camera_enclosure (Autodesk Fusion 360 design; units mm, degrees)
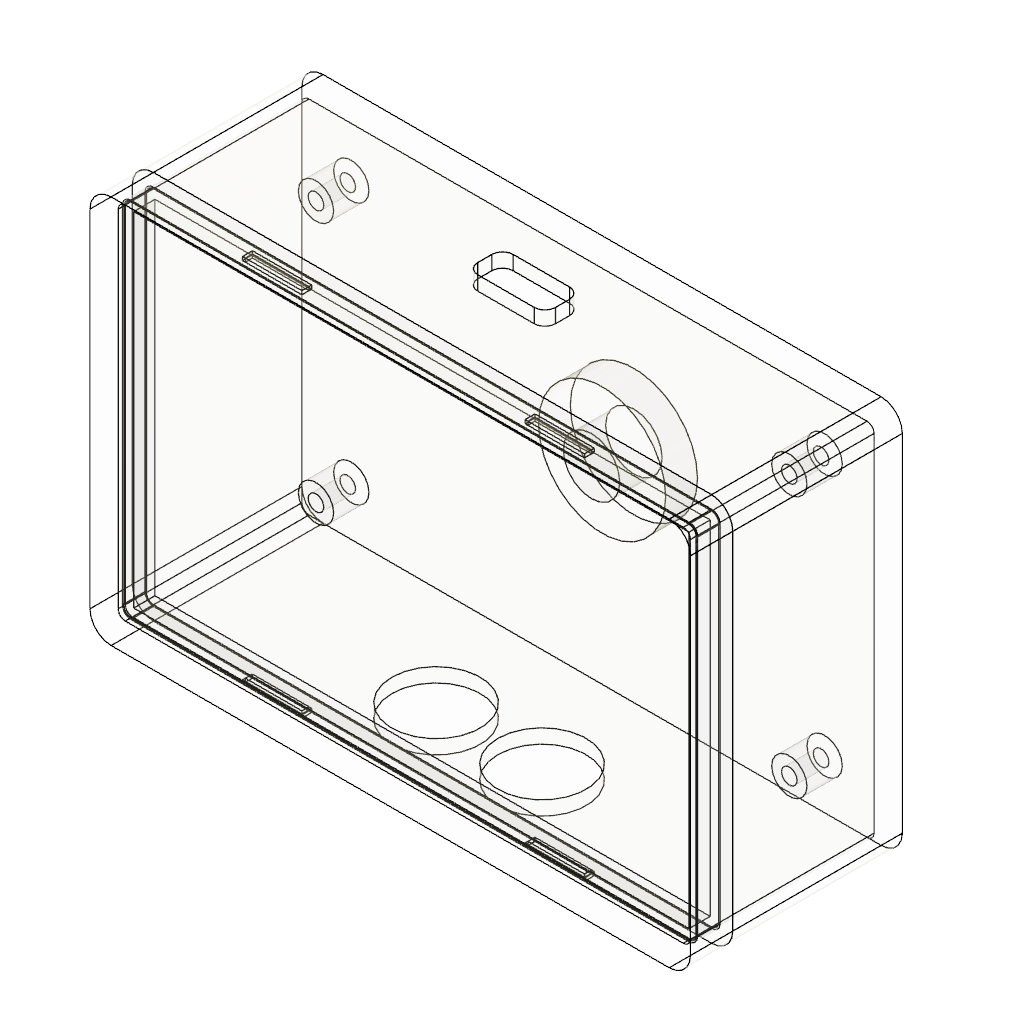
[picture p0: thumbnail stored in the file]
part number: 2026-10-16-16-51-44-539
parameter "User Parameter" = 0 (= "job ae3369b9")
parameter "encL" = 85 comment "job ae3369b9"
parameter "encW" = 55 comment "job ae3369b9"
parameter "encH" = 30 comment "job ae3369b9"
parameter "wall" = 2 comment "job ae3369b9"
parameter "Rv" = 3 comment "job ae3369b9"
parameter "split" = 24 comment "job ae3369b9"
parameter "lipT" = 1.2 comment "job ae3369b9"
parameter "lipH" = 3 comment "job ae3369b9"
parameter "clr" = 0.2 comment "job ae3369b9"
parameter "lensD" = 12.5 comment "job ae3369b9"
parameter "lensPitch" = 15 comment "job ae3369b9"
parameter "lensZ" = 16 comment "job ae3369b9"
parameter "usbW" = 11 comment "job ae3369b9"
parameter "usbH" = 5 comment "job ae3369b9"
parameter "usbR" = 1.5 comment "job ae3369b9"
parameter "usbZ" = 8.6 comment "job ae3369b9"
parameter "soOD" = 5 comment "job ae3369b9"
parameter "soID" = 2.2 comment "job ae3369b9"
parameter "soH" = 5 comment "job ae3369b9"
parameter "soPx" = 67 comment "job ae3369b9"
parameter "soPy" = 37 comment "job ae3369b9"
parameter "bossD" = 18 comment "job ae3369b9"
parameter "bossH" = 4.5 comment "job ae3369b9"
parameter "insD" = 8 comment "job ae3369b9"
parameter "insDepth" = 6 comment "job ae3369b9"
parameter "snapL" = 8 comment "job ae3369b9"
parameter "snapP" = 0.5 comment "job ae3369b9"
parameter "snapX" = 20 comment "job ae3369b9"
sketch "Outline" plane through (0, 0, 0) normal (0, 0, 1) x axis (1, 0, 0)
  line L1 (-42.5, 27.5) -> (42.5, 27.5)
  line L2 (-42.5, -27.5) -> (-42.5, 27.5)
  line L3 (42.5, -27.5) -> (-42.5, -27.5)
  line L4 (42.5, 27.5) -> (42.5, -27.5)
extrude "Extrude1" new body sketch "Outline" along normal blind 30 (= "encH") bodies "Tub"
fillet "Fillet1" radius 3 (= "Rv")
shell "Shell1" innerThickness 2 (= "wall")
work_plane "WorkPlane1" sketch "LidClearance" AlongDistance 2 (= "wall") ExtraOffset 0
sketch "Standoffs" plane through (0, 0, 2) normal (0, 0, 1) x axis (1, 0, 0)
  circle C1 centre (-33.5, -18.5) radius 2.5
  circle C2 centre (-33.5, 18.5) radius 2.5
  circle C3 centre (33.5, -18.5) radius 2.5
  circle C4 centre (33.5, 18.5) radius 2.5
extrude "Extrude2" add sketch "Standoffs" along normal blind 5 (= "soH")
work_plane "WorkPlane2" sketch "LidClearance" AlongDistance 7 (= "wall + soH") ExtraOffset 0
sketch "StandoffHoles" plane through (0, 0, 7) normal (0, 0, 1) x axis (1, 0, 0)
  circle C1 centre (-33.5, -18.5) radius 1.1
  circle C2 centre (-33.5, 18.5) radius 1.1
  circle C3 centre (33.5, -18.5) radius 1.1
  circle C4 centre (33.5, 18.5) radius 1.1
extrude "Extrude3" cut sketch "StandoffHoles" against normal blind 4.5 (magnitude of "-( soH - 0.5 mm )")
sketch "TripodBoss" plane through (0, 0, 0) normal (0, 0, 1) x axis (1, 0, 0)
  circle C1 centre (0, 0) radius 9
extrude "Extrude4" add sketch "TripodBoss" no distance stored
work_plane "WorkPlane3" sketch "LidClearance" ExtraOffset 0
sketch "InsertPocket" plane through (0, 0, -4.5) normal (0, 0, 1) x axis (1, 0, 0)
  circle C1 centre (0, 0) radius 4
extrude "Extrude5" cut sketch "InsertPocket" along normal blind 6 (= "insDepth")
sketch "LensHoles" plane through (0, -27.5, 0) normal (0, -1, 0) x axis (1, 0, 0)
  line L1 (-39.5, 0) -> (-39.5, 30)
  line L2 (39.5, 0) -> (-39.5, 0)
  line L3 (39.5, 30) -> (39.5, 0)
  line L4 (-39.5, 30) -> (39.5, 30)
  circle C1 centre (-7.5, 16) radius 6.25
  circle C2 centre (7.5, 16) radius 6.25
extrude "Extrude6" cut sketch "LensHoles" profile of C1 C2 against normal blind 3 (magnitude of "-( wall + 1 mm )")
sketch "USBC" plane through (0, 27.5, 0) normal (0, 1, 0) x axis (-1, 0, 0)
  line L1 (-39.5, 0) -> (-39.5, 30)
  line L2 (39.5, 0) -> (-39.5, 0)
  line L3 (39.5, 30) -> (39.5, 0)
  line L4 (-39.5, 30) -> (39.5, 30)
  line L5 (4, 13.6) -> (-4, 13.6)
  line L6 (5.5, 10.1) -> (5.5, 12.1)
  line L7 (-4, 8.6) -> (4, 8.6)
  line L8 (-5.5, 12.1) -> (-5.5, 10.1)
  arc A1 centre (4, 12.1) radius 1.5 clockwise from (4, 13.6) to (5.5, 12.1)
  arc A2 centre (4, 10.1) radius 1.5 clockwise from (5.5, 10.1) to (4, 8.6)
  arc A3 centre (-4, 10.1) radius 1.5 clockwise from (-4, 8.6) to (-5.5, 10.1)
  arc A4 centre (-4, 12.1) radius 1.5 clockwise from (-5.5, 12.1) to (-4, 13.6)
  tangent L5 A1
  tangent L6 A1
  tangent L6 A2
  tangent L7 A2
  tangent L7 A3
  tangent L8 A3
  tangent L8 A4
  tangent L5 A4
extrude "Extrude7" cut sketch "USBC" profile of L5 L6 L7 L8 A1 A2 A3 A4 against normal blind 3 (magnitude of "-( wall + 1 mm )")
work_plane "WorkPlane4" AlongDistance 24 (= "split") ExtraOffset 0
split "Split1" bodies "Lid"
sketch "Lip" plane through (0, 0, 24) normal (0, 0, 1) x axis (1, 0, 0)
  line L1 (-39.5, 25.5) -> (39.5, 25.5)
  line L2 (-40.5, -24.5) -> (-40.5, 24.5)
  line L3 (39.5, -25.5) -> (-39.5, -25.5)
  line L4 (40.5, 24.5) -> (40.5, -24.5)
  line L5 (-39.3, 24.3) -> (39.3, 24.3)
  line L6 (-39.3, -24.3) -> (-39.3, 24.3)
  line L7 (39.3, -24.3) -> (-39.3, -24.3)
  line L8 (39.3, 24.3) -> (39.3, -24.3)
  arc A1 centre (-39.5, 24.5) radius 1 clockwise from (-40.5, 24.5) to (-39.5, 25.5)
  arc A2 centre (-39.5, -24.5) radius 1 clockwise from (-39.5, -25.5) to (-40.5, -24.5)
  arc A3 centre (39.5, -24.5) radius 1 clockwise from (40.5, -24.5) to (39.5, -25.5)
  arc A4 centre (39.5, 24.5) radius 1 clockwise from (39.5, 25.5) to (40.5, 24.5)
  tangent L1 A1
  tangent L2 A1
  tangent L2 A2
  tangent L3 A2
  tangent L3 A3
  tangent L4 A3
  tangent L4 A4
  tangent L1 A4
extrude "Extrude8" add sketch "Lip" along normal blind 3 (= "lipH")
sketch "LidClearance" plane through (0, 0, 24) normal (0, 0, 1) x axis (1, 0, 0)
  line L1 (-39.5, 25.7) -> (39.5, 25.7)
  line L2 (-40.7, -24.5) -> (-40.7, 24.5)
  line L3 (39.5, -25.7) -> (-39.5, -25.7)
  line L4 (40.7, 24.5) -> (40.7, -24.5)
  line L5 (-38.3, 23.3) -> (38.3, 23.3)
  line L6 (-38.3, -23.3) -> (-38.3, 23.3)
  line L7 (38.3, -23.3) -> (-38.3, -23.3)
  line L8 (38.3, 23.3) -> (38.3, -23.3)
  arc A1 centre (-39.5, 24.5) radius 1.2 clockwise from (-40.7, 24.5) to (-39.5, 25.7)
  arc A2 centre (-39.5, -24.5) radius 1.2 clockwise from (-39.5, -25.7) to (-40.7, -24.5)
  arc A3 centre (39.5, -24.5) radius 1.2 clockwise from (40.7, -24.5) to (39.5, -25.7)
  arc A4 centre (39.5, 24.5) radius 1.2 clockwise from (39.5, 25.7) to (40.7, 24.5)
  tangent L1 A1
  tangent L2 A1
  tangent L2 A2
  tangent L3 A2
  tangent L3 A3
  tangent L4 A3
  tangent L4 A4
  tangent L1 A4
extrude "Extrude9" cut sketch "LidClearance" along normal blind 3.2 (= "lipH + clr")
work_plane "WorkPlane5" AlongDistance 25.5 (= "split + 1.5 mm") ExtraOffset 0
sketch "SnapBumps" plane through (0, 0, 25.5) normal (0, 0, 1) x axis (1, 0, 0)
  line L1 (-24, -25.5) -> (-16, -25.5)
  line L2 (-24, -26) -> (-24, -25.5)
  line L3 (-16, -26) -> (-24, -26)
  line L4 (-16, -25.5) -> (-16, -26)
  line L5 (-24, 26) -> (-16, 26)
  line L6 (-24, 25.5) -> (-24, 26)
  line L7 (-16, 25.5) -> (-24, 25.5)
  line L8 (-16, 26) -> (-16, 25.5)
  line L9 (16, -25.5) -> (24, -25.5)
  line L10 (16, -26) -> (16, -25.5)
  line L11 (24, -26) -> (16, -26)
  line L12 (24, -25.5) -> (24, -26)
  line L13 (16, 26) -> (24, 26)
  line L14 (16, 25.5) -> (16, 26)
  line L15 (24, 25.5) -> (16, 25.5)
  line L16 (24, 26) -> (24, 25.5)
extrude "Extrude10" add sketch "SnapBumps" along normal blind 1
work_plane "WorkPlane6" AlongDistance 25.3 (= "split + 1.5 mm - clr") ExtraOffset 0
sketch "SnapGrooves" plane through (0, 0, 25.3) normal (0, 0, 1) x axis (1, 0, 0)
  line L1 (-24.2, -25.5) -> (-15.8, -25.5)
  line L2 (-24.2, -26.2) -> (-24.2, -25.5)
  line L3 (-15.8, -26.2) -> (-24.2, -26.2)
  line L4 (-15.8, -25.5) -> (-15.8, -26.2)
  line L5 (-24.2, 26.2) -> (-15.8, 26.2)
  line L6 (-24.2, 25.5) -> (-24.2, 26.2)
  line L7 (-15.8, 25.5) -> (-24.2, 25.5)
  line L8 (-15.8, 26.2) -> (-15.8, 25.5)
  line L9 (15.8, -25.5) -> (24.2, -25.5)
  line L10 (15.8, -26.2) -> (15.8, -25.5)
  line L11 (24.2, -26.2) -> (15.8, -26.2)
  line L12 (24.2, -25.5) -> (24.2, -26.2)
  line L13 (15.8, 26.2) -> (24.2, 26.2)
  line L14 (15.8, 25.5) -> (15.8, 26.2)
  line L15 (24.2, 25.5) -> (15.8, 25.5)
  line L16 (24.2, 26.2) -> (24.2, 25.5)
extrude "Extrude11" cut sketch "SnapGrooves" along normal blind 1.4 (= "1 mm + 2 * clr")
named bodies: "Tub", "Lid"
